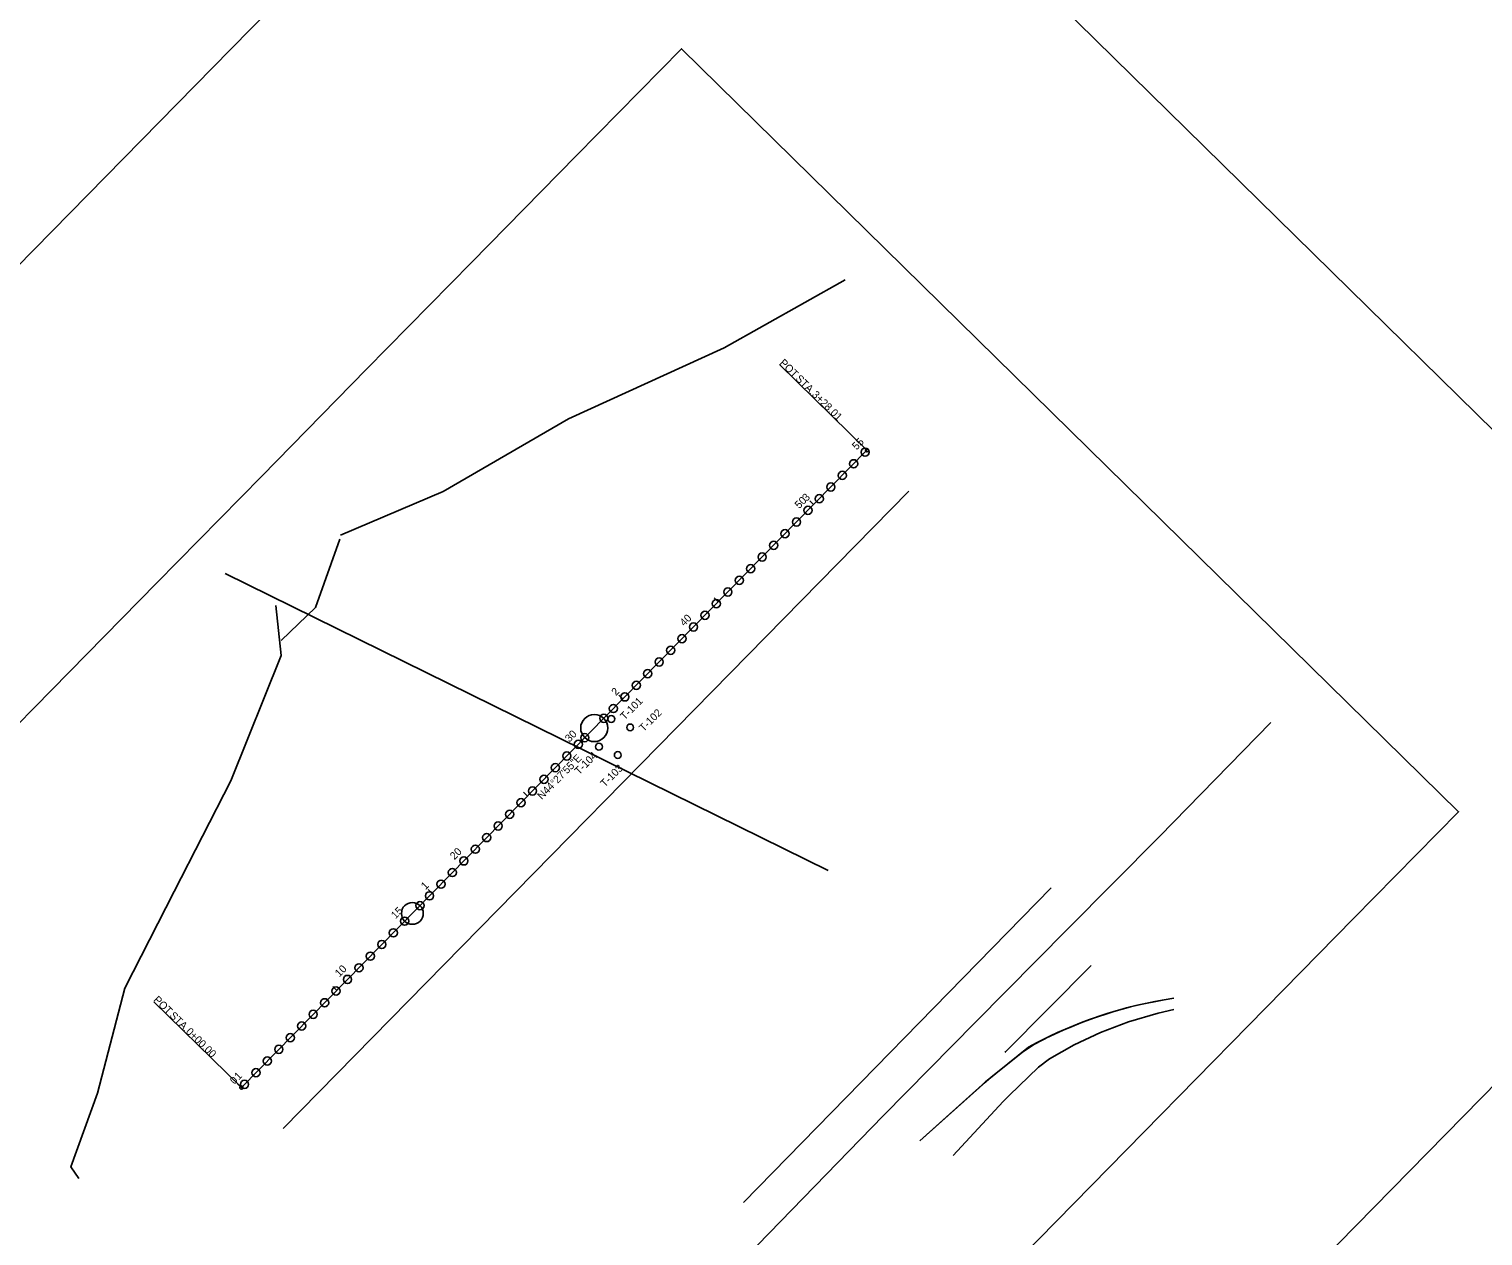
# Model space of a CAD drawing. Extents: x 143926 to 145461, y 370955 to 372184.
# Drawn here: x 144566 to 145099, y 371460 to 371904 of the extents above; entities that cross this region are included whole.
import ezdxf

# ---------------------------------------------------------------- set-up
doc = ezdxf.new("R2010")
doc.units = 0
for name, color, linetype in [('_CIVIL_CONSTRUCTION', 7, 'Continuous'), ('DR_P_Ditch', 7, 'Continuous'), ('DT_P_Tie', 7, 'Continuous'), ('GE_P_Alignment', 7, 'Continuous'), ('GT_Project_Text', 7, 'Continuous'), ('PM_P_Edge_Line', 7, 'Continuous'), ('RW_X_CL', 7, 'Continuous'), ('SC_Scratch1', 7, 'Continuous'), ('SC_Scratch6', 7, 'Continuous'), ('SH_Named_Boundary', 7, 'Continuous')]:
    doc.layers.add(name, color=color, linetype=linetype)

msp = doc.modelspace()

# ---------------------------------------------------------------- linework, layer by layer
at = {"layer": '_CIVIL_CONSTRUCTION'}
msp.add_lwpolyline([(144923.94, 371527.67), (144924.16, 371527.9), (144955.54, 371559.62)], dxfattribs=at)
at = {"layer": 'DR_P_Ditch'}
for p, q in [((144916.79, 371516.84), (144932.62, 371529.57)), ((144892.69, 371495.1), (144916.85, 371516.89)), ((144892.69, 371495.1), (144916.79, 371516.84))]:
    msp.add_line(p, q, dxfattribs=at)
for points in [[(144904.96, 371489.76), (144923.21, 371509.6), (144925.44, 371511.81), (144936.2, 371522.26), (144940.23, 371525.32), (144949.33, 371530.39), (144959, 371534.91), (144969.28, 371538.84), (144980.23, 371542.1), (144985.99, 371543.44)], [(144896.25, 371498.31), (144916.29, 371516.39), (144918.73, 371518.4), (144930.5, 371527.87), (144934.73, 371530.72)]]:
    msp.add_lwpolyline(points, dxfattribs=at)
for start, end in [(98.4074, 118.7731), (99.6832, 117.9071)]:
    msp.add_arc((145009.18, 371390.15), 159.07, start, end, dxfattribs=at)
at = {"layer": 'DT_P_Tie'}
for p, q in [((144670.73, 371691.03), (144679.67, 371716.15)), ((144658.11, 371678.98), (144670.73, 371691.03))]:
    msp.add_line(p, q, dxfattribs=at)
for points in [[(144865.22, 371811.42), (144820.84, 371786.47), (144763.61, 371760.33), (144717.59, 371733.72), (144679.86, 371717.65)], [(144656.18, 371691.77), (144658.07, 371673.42), (144639.67, 371627.35), (144618.77, 371586.69), (144600.75, 371551.24), (144590.67, 371512.68), (144580.89, 371485.55), (144583.82, 371481.32)]]:
    msp.add_lwpolyline(points, dxfattribs=at)
at = {"layer": 'GE_P_Alignment'}
msp.add_line((144643.5, 371514.74), (144873.26, 371748.83), dxfattribs=at)
at = {"layer": 'GT_Project_Text'}
for centre, radius in [((144872.58, 371748.14), 1.5), ((144864.18, 371739.58), 1.5), ((144868.38, 371743.86), 1.5), ((144859.98, 371735.3), 1.5), ((144855.77, 371731.01), 1.5), ((144851.57, 371726.73), 1.5), ((144843.16, 371718.17), 1.5), ((144847.37, 371722.45), 1.5), ((144838.96, 371713.89), 1.5), ((144834.76, 371709.6), 1.5), ((144830.56, 371705.32), 1.5), ((144822.15, 371696.76), 1.5), ((144826.35, 371701.04), 1.5), ((144817.95, 371692.47), 1.5), ((144813.74, 371688.19), 1.5), ((144809.54, 371683.91), 1.5), ((144801.14, 371675.35), 1.5), ((144805.34, 371679.63), 1.5), ((144796.93, 371671.06), 1.5), ((144792.73, 371666.78), 1.5), ((144788.53, 371662.5), 1.5), ((144780.12, 371653.94), 1.5), ((144784.32, 371658.22), 1.5), ((144776.62, 371650.37), 1.5), ((144779.36, 371650.11), 1.25), ((144769.61, 371643.23), 1.5), ((144786.28, 371647.02), 1.25), ((144767.23, 371640.8), 1.5), ((144774.82, 371639.94), 1.25), ((144758.83, 371632.24), 1.5), ((144763.03, 371636.52), 1.5), ((144781.74, 371636.86), 1.25), ((144754.62, 371627.96), 1.5), ((144750.42, 371623.68), 1.5), ((144746.22, 371619.39), 1.5), ((144737.81, 371610.83), 1.5), ((144742.01, 371615.11), 1.5), ((144733.61, 371606.55), 1.5), ((144729.41, 371602.27), 1.5), ((144725.2, 371597.98), 1.5), ((144716.8, 371589.42), 1.5), ((144721, 371593.7), 1.5), ((144712.6, 371585.14), 1.5), ((144709.09, 371581.57), 1.5), ((144703.49, 371575.86), 1.5), ((144699.29, 371571.58), 1.5), ((144690.88, 371563.01), 1.5), ((144695.08, 371567.3), 1.5), ((144686.68, 371558.73), 1.5), ((144682.47, 371554.45), 1.5), ((144678.27, 371550.17), 1.5), ((144669.87, 371541.6), 1.5), ((144674.07, 371545.88), 1.5), ((144665.66, 371537.32), 1.5), ((144661.46, 371533.04), 1.5), ((144657.26, 371528.76), 1.5), ((144648.85, 371520.19), 1.5), ((144653.05, 371524.47), 1.5), ((144644.65, 371515.91), 1.5)]:
    msp.add_circle(centre, radius, dxfattribs=at)
at = {"layer": 'PM_P_Edge_Line'}
for points in [[(145021.61, 371648.85), (144980.63, 371606.92), (144946.95, 371572.97), (144913.14, 371538.79), (144879.16, 371504.38), (144845.7, 371469.79), (144812.12, 371435.33), (144775.06, 371398.24), (144739.52, 371361.45), (144706.53, 371327.95), (144671.45, 371292.41)], [(144963.91, 371590.06), (144946.95, 371572.97), (144913.14, 371538.79), (144879.16, 371504.38), (144845.7, 371469.79), (144812.12, 371435.33), (144775.06, 371398.24), (144739.52, 371361.45), (144706.53, 371327.95), (144671.45, 371292.41)]]:
    msp.add_lwpolyline(points, dxfattribs=at)
at = {"layer": 'RW_X_CL'}
msp.add_line((144637.54, 371703.58), (144859.05, 371594.42), dxfattribs=at)
at = {"layer": 'SC_Scratch1'}
for p, q in [((144873.26, 371748.83), (144841.14, 371780.35)), ((144658.84, 371499.68), (144888.6, 371733.77)), ((144853.64, 371728.84), (144852.22, 371730.24)), ((144818.62, 371693.16), (144817.19, 371694.56)), ((144783.6, 371657.48), (144782.17, 371658.88)), ((144748.57, 371621.79), (144747.14, 371623.19)), ((144713.55, 371586.11), (144712.12, 371587.51)), ((144827.85, 371472.52), (144940.9, 371588.1)), ((144678.52, 371550.42), (144677.1, 371551.82)), ((144643.5, 371514.74), (144611.38, 371546.26)), ((144643.5, 371514.74), (144642.07, 371516.14))]:
    msp.add_line(p, q, dxfattribs=at)
msp.add_lwpolyline([(144644.65, 371515.91), (144648.85, 371520.19), (144653.05, 371524.47)], dxfattribs=at)
for centre, radius in [((144873.26, 371748.83), 0.6), ((144773.12, 371646.8), 5), ((144706.29, 371578.71), 4), ((144643.5, 371514.74), 0.6)]:
    msp.add_circle(centre, radius, dxfattribs=at)
at = {"layer": 'SH_Named_Boundary'}
for points in [[(144271.74, 371521.55), (144698.13, 371102.79), (144750.68, 371156.3), (144803.23, 371209.81), (144855.78, 371263.32), (144908.34, 371316.83), (144960.89, 371370.34), (145013.44, 371423.85), (145065.99, 371477.36), (145118.55, 371530.86), (145171.1, 371584.37), (145223.65, 371637.88), (144797.27, 372056.64), (144744.72, 372003.13), (144692.16, 371949.62), (144639.61, 371896.11), (144587.06, 371842.6), (144534.51, 371789.09), (144481.95, 371735.59), (144429.4, 371682.08), (144376.85, 371628.57), (144324.3, 371575.06)], [(144419.73, 371503.89), (144705.11, 371223.61), (144743.65, 371262.85), (144782.19, 371302.09), (144820.73, 371341.33), (144859.27, 371380.57), (144897.81, 371419.81), (144936.35, 371459.05), (144974.88, 371498.29), (145013.42, 371537.53), (145051.96, 371576.77), (145090.5, 371616.01), (144805.12, 371896.29), (144766.58, 371857.05), (144728.04, 371817.81), (144689.5, 371778.57), (144650.96, 371739.33), (144612.42, 371700.09), (144573.89, 371660.85), (144535.35, 371621.61), (144496.81, 371582.37), (144458.27, 371543.13)]]:
    msp.add_lwpolyline(points, close=True, dxfattribs=at)

# ---------------------------------------------------------------- texts
at = {"layer": 'SC_Scratch1'}
for s, rotation, p in [('POT', 315.5348, (144840.91, 371780.64)), (' STA. ', 315.5348, (144846.05, 371775.6)), ('3+28.01', 315.5348, (144852.8, 371768.97)), ('3', 45.5348, (144851.13, 371729.85)), ('2', 45.5348, (144781.08, 371658.48)), ('N44°27\'55"E', 45.5348, (144753.85, 371620.31)), ('1', 45.5348, (144711.12, 371587.2)), ('POT', 315.5348, (144611.01, 371546.69)), (' STA. ', 315.5348, (144616.15, 371541.64)), ('0+00.00', 315.5348, (144622.9, 371535.02)), ('0', 45.5348, (144640.94, 371515.7))]:
    msp.add_text(s, height=2.8, rotation=rotation, dxfattribs=at).set_placement(p)
at = {"layer": 'SC_Scratch6'}
for s, p in [('55', (144869.43, 371748.74)), ('50', (144848.37, 371727.18)), ('40', (144806.15, 371683.97)), ('T-101', (144784.27, 371649.51)), ('T-102', (144791.22, 371645.22)), ('30', (144763.98, 371641.4)), ('T-104', (144767.53, 371629.45)), ('T-103', (144776.98, 371624.84)), ('20', (144721.75, 371598.21)), ('15', (144700.11, 371576.47)), ('10', (144679.48, 371555.13)), ('1', (144642.51, 371517.32))]:
    msp.add_text(s, height=2.8, rotation=45, dxfattribs=at).set_placement(p)

doc.saveas('drawing.dxf')
